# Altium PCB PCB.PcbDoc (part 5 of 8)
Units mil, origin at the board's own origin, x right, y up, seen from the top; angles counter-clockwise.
Board outline 11229.24 x 7764.43 mil, 14 copper layers (Top Layer, GND1, Signal 1, GND2, Signal 2, GND3, Singal 3, Power 1, GND4, Power 2, GND5, Power 3, GND6, Bottom Layer), stack 91.892 mil thick; 877 components, 305 nets, 2660 pads, 2851 vias.
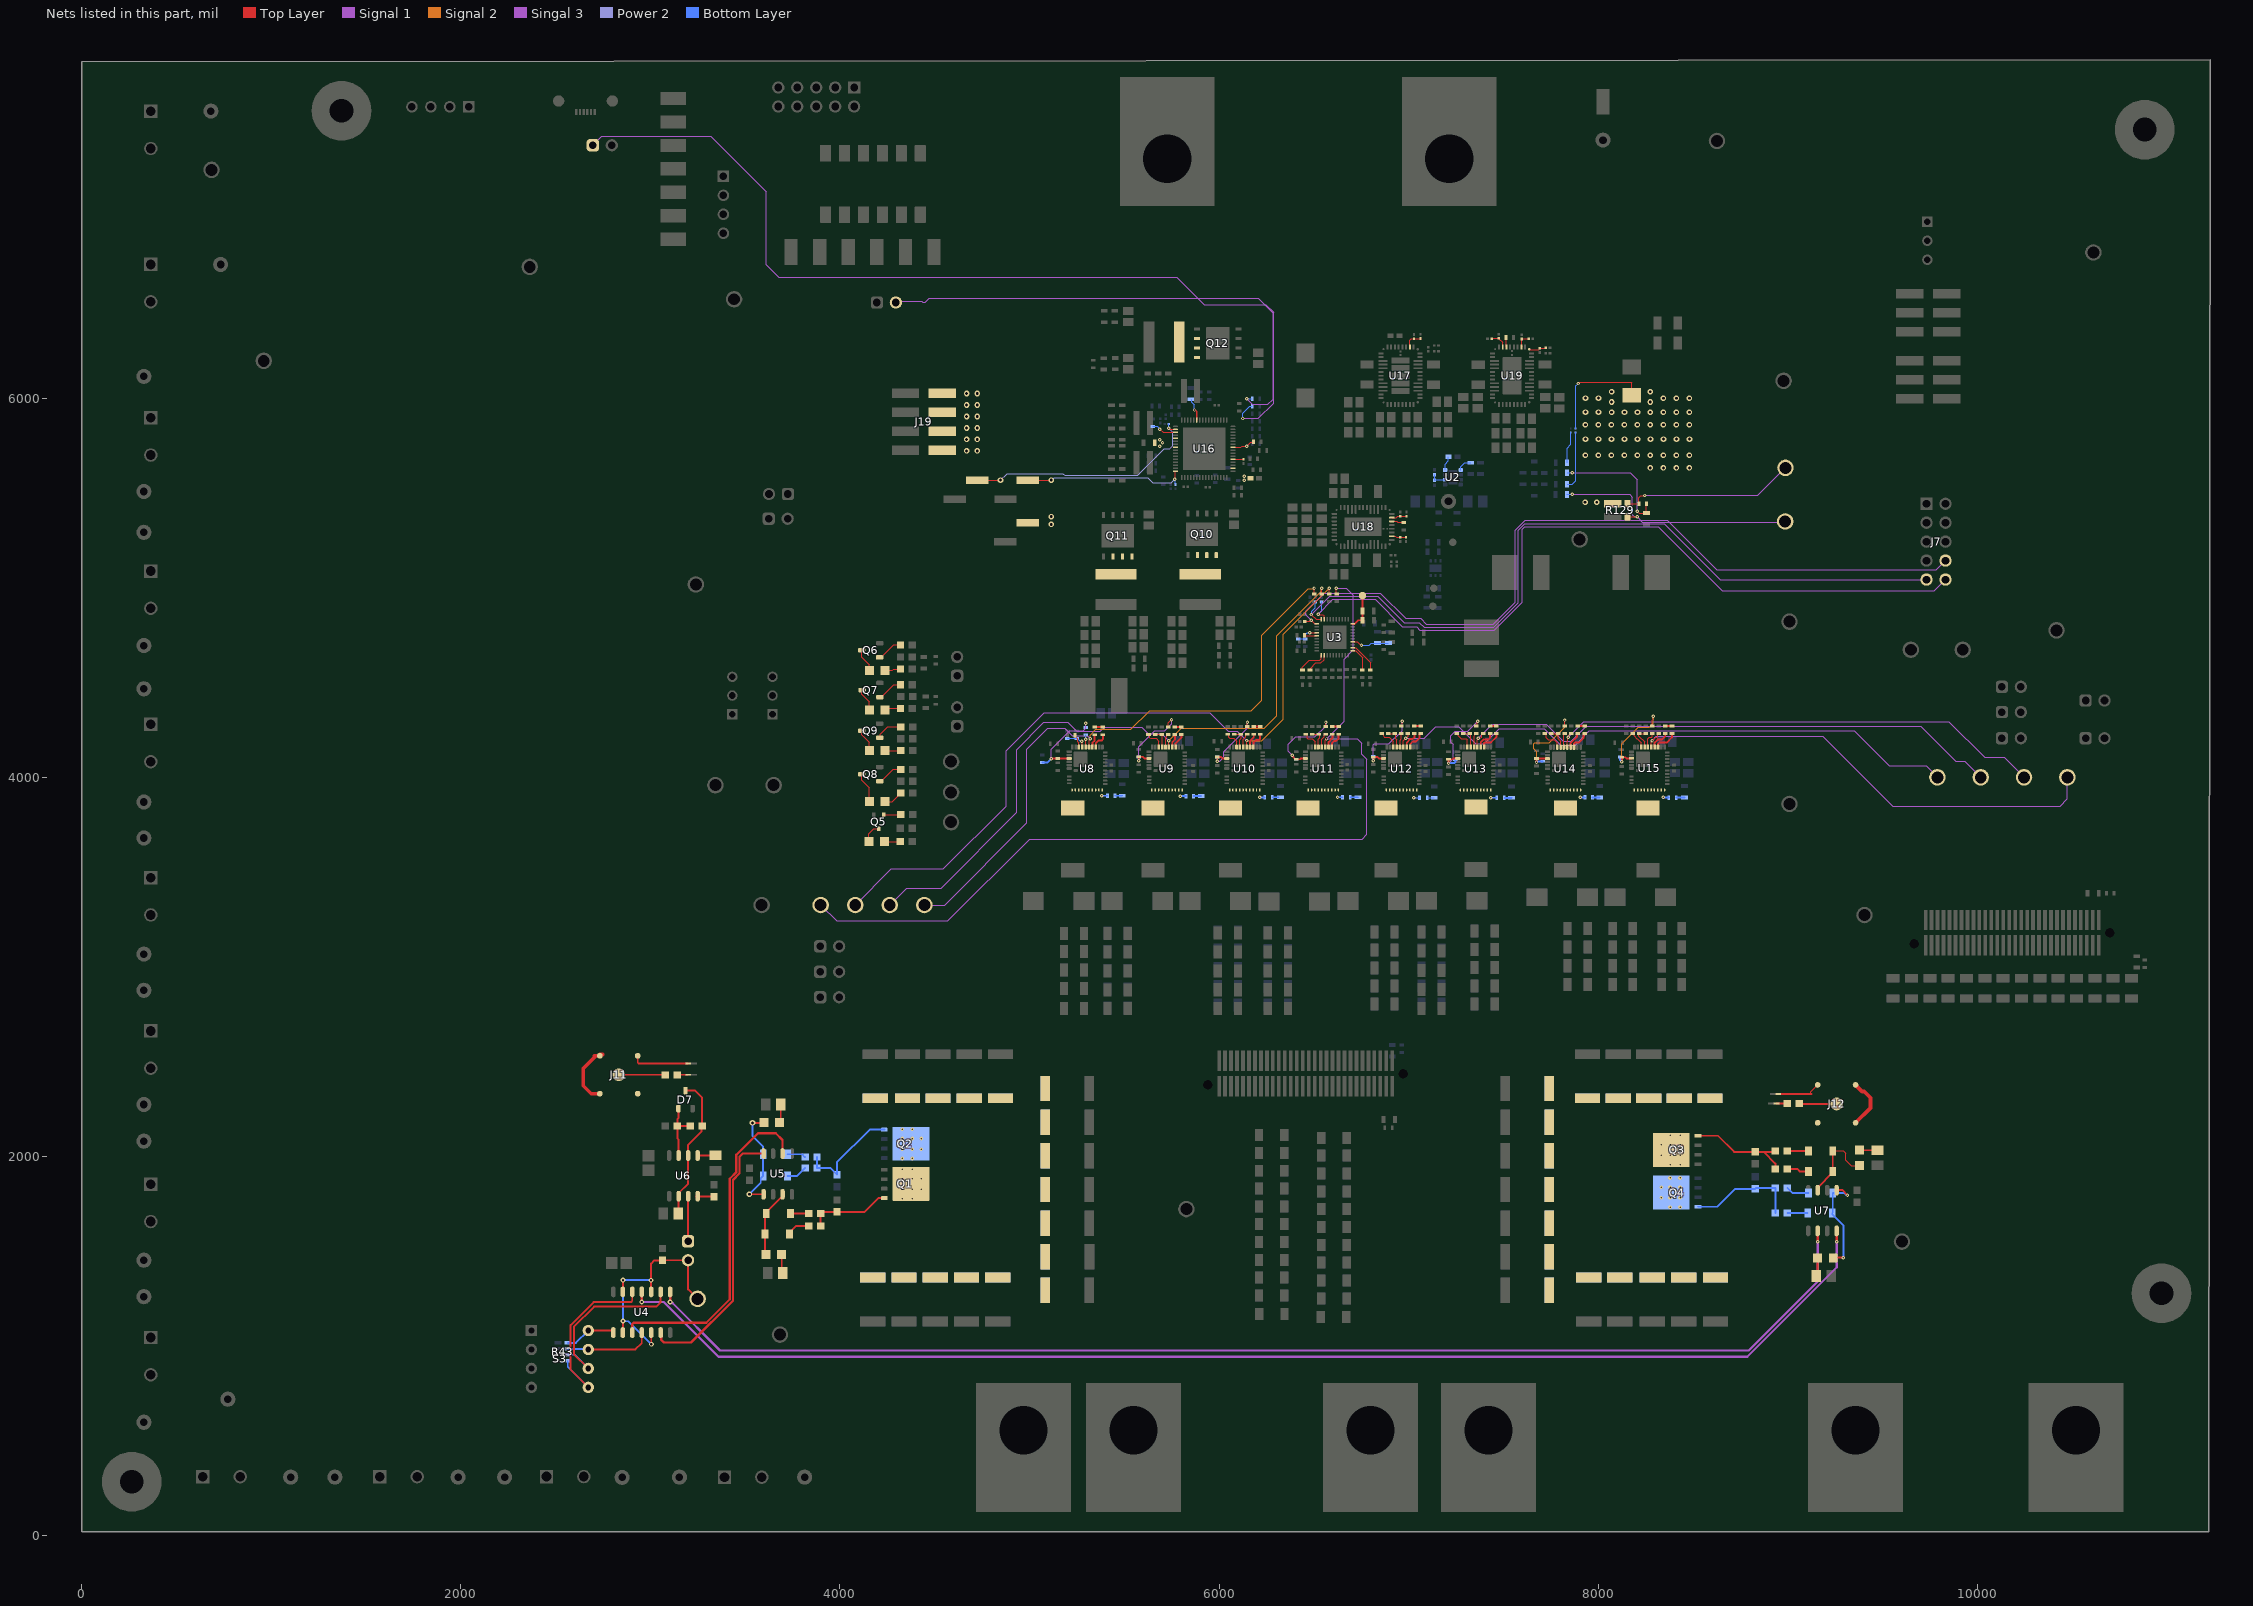
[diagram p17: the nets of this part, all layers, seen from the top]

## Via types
v1: diameter 30, hole 15, Top Layer to Bottom Layer, 1251 vias
v2: diameter 18, hole 8, Top Layer to Bottom Layer, tented both sides, 472 vias
v3: diameter 32, hole 16, Top Layer to Bottom Layer, 464 vias
v4: diameter 30, hole 15, Top Layer to Bottom Layer, tented both sides, 326 vias
v5: diameter 19.68, hole 7.87, Top Layer to Bottom Layer, 323 vias
v6: diameter 26, hole 12, Top Layer to Bottom Layer, tented both sides, 12 vias
v7: diameter 14, hole 6, Top Layer to Bottom Layer, tented both sides, 2 vias
v8: diameter 18, hole 8, Top Layer to Bottom Layer, 1 vias

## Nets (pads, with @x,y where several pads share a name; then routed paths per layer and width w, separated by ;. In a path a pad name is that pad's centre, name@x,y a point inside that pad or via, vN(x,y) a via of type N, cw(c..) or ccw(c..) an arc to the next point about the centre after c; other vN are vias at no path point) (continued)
MODE2-U4: R242.1 R245.1 U19.38 | length 89.1
  Top Layer w6: U19.38@7639.91,6257.54 7641.31,6256.14 7647.41,6256.14 7647.91,6256.64 7685.53,6256.64 7688.2,6259.31 7688.99,6259.31 7692.29,6262.61 R242.1@7692.29,6263.4 7693.17,6264.28 7723.3,6264.28 R245.1@7724.18,6265.16
NetC8_1: C8.1 U2.8 | length 77.5
  Bottom Layer w6: U2.8@7192.15,5620.99 7192.15,5652.53 7210.35,5670.72 C8.1@7210.35,5691
NetC16_1: C16.1 R17.1 TP8.1 U3.40 | length 189.8
  Top Layer w10: U3.40@6704.62,4809.13 6715.64,4809.13 6735.12,4828.6 C16.1@6756.79,4828.6 6756.79,4876.58 R17.1@6756.32,4877.05 6756.32,4957.32 TP8.1@6756.8,4957.8
NetC28_1: C28.1 U6.5 | length 95.5
  Top Layer w10: U6.5@3249.16,2004.66 3344.37,2004.66 C28.1@3344.56,2004.85
NetC29_1: C29.1 D7.3 R117.1 U6.2 U6.6 | length 766.5
  Top Layer w10: C29.1@3146.64,1699.1 3149.16,1701.62 U6.2@3149.16,1790.09 3149.16,1806.83 3199.16,1856.83 U6.6@3199.16,2004.66 3199.16,2061.16 3269,2131 3269,2155.56 R117.1@3273.18,2159.73 3273.18,2310.05 3236.49,2346.74 D7.3@3185.24,2346.74
NetC82_1: C82.1 R26.1 R128.1 | length 654.6
  Top Layer w6: v2(8205.63,5402.4) 8208.88,5402.4 8217.78,5393.5 C82.1@8254.9,5393.5 R128.1@8254.9,5442.9
  Singal 3 w6: v2(7864.1,5606) 7864.39,5605.71 8169.73,5605.71 8205.63,5569.8 v2(8205.63,5402.4)
  Bottom Layer w6: R26.1@7835.91,5605.71 7836.2,5606 v2(7864.1,5606)
NetC171_1: C171.1 L2.1 U8.10 U8.11 U8.12 U8.13 U8.14 U8.15 U8.16 U8.17 U8.18 U8.19 | length 31.5
  Bottom Layer w10: v2@5380.43,3902.65 v2(5380.37,3902.59) C171.1@5411.78,3902.59
NetC171_2: C171.2 R147.2 | length 37.5
  Bottom Layer w6: R147.2@5488.57,3902.59 R147.2@5488.63,3902.65
  Bottom Layer w10: C171.2@5452.02,3902.36 C171.2@5451.78,3902.59 R147.2@5488.57,3902.59 ; R147.2@5488.63,3902.65 R147.2@5488.87,3902.41
NetC184_1: C184.1 R148.2 R152.2 U8.3 | length 474.5
  Top Layer w10: v2(5115.5,4098.1) 5116.63,4099.23 C184.1@5148.25,4099.23 U8.3@5209.67,4099.24
  Signal 1 w6: v2(5115.5,4098.1) 5115.5,4148.27 5212.53,4245.3 5283.1,4245.3 5297.36,4259.56 v2(5297.36,4284.39)
  Bottom Layer w6: R148.2@5297.36,4263.12 v2(5297.36,4284.39)
  Bottom Layer w10: R152.2@5068.1,4078.26 5095.66,4078.26 v2(5115.5,4098.1)
NetC185_2: C185.2 R153.2 U8.36 | length 113.1
  Top Layer w6: v2@5277.44,4188.84 5277.44,4160.42 U8.36@5278.57,4159.28
  Bottom Layer w6: C185.2@5199.29,4204.65 R153.2@5248.68,4204.65 5253.18,4204.65 5265.56,4192.27 5274,4192.27 v2(5276.3,4189.97)
NetC186_1: C186.1 R154.2 | length 43.9
  Top Layer w10: C186.1@5343.53,4264.47 R154.2@5387.38,4264.47
NetC186_2: C186.2 U8.33 | length 70.3
  Top Layer w10: U8.33@5331.72,4159.28 5331.72,4181.76 5343.76,4193.81 5343.76,4224.24 C186.2@5343.53,4224.47
NetC187_1: C187.1 L3.1 U9.10 U9.11 U9.12 U9.13 U9.14 U9.15 U9.16 U9.17 U9.18 U9.19 | length 31.3
  Bottom Layer w6: C187.1@5825.09,3900.84 C187.1@5826.09,3901.84
  Bottom Layer w10: v2(5795.18,3900.84) C187.1@5825.09,3900.84
NetC187_2: C187.2 R155.2 | length 42.7
  Bottom Layer w6: R155.2@5905.68,3900.84 R155.2@5906.69,3901.84
  Bottom Layer w10: C187.2@5865.09,3900.84 R155.2@5905.68,3900.84 ; C187.2@5866.09,3901.84 C187.2@5866.61,3901.33
NetC198_1: C198.1 R156.2 R159.2 U9.3 | length 463.9
  Top Layer w6: R156.2@5731.89,4265.93 5731.89,4286.8 5749.02,4303.93 v2(5749.2,4303.93)
  Top Layer w10: v2(5576.28,4087.06) 5576.28,4108.05 C198.1@5576.35,4108.13 5596.81,4108.13 5599.22,4105.72 5605.7,4099.24 U9.3@5630.91,4099.24
  Signal 1 w6: v2(5576.28,4087.06) 5576.28,4161.03 5660.55,4245.3 5712.92,4245.3 5749.2,4281.58 v2(5749.2,4303.93)
  Bottom Layer w10: v2(5576.28,4087.06) R159.2@5576.28,4107.15
NetC201_2: C201.2 R161.2 U9.36 | length 98
  Top Layer w6: C201.2@5668.57,4225.93 R161.2@5699.41,4225.93 ; R161.2@5699.51,4225.93 R161.2@5700.71,4224.73 ; U9.36@5699.81,4159.28 R161.2@5699.81,4224.73
NetC202_1: C202.1 R162.2 | length 33.2
  Top Layer w10: C202.1@5768.61,4265.93 R162.2@5801.85,4265.93
NetC202_2: C202.2 U9.33 | length 72.3
  Top Layer w10: U9.33@5752.96,4159.28 5752.96,4185.65 5766.57,4199.25 C202.2@5766.57,4225.93
NetC203_1: C203.1 L4.1 U10.10 U10.11 U10.12 U10.13 U10.14 U10.15 U10.16 U10.17 U10.18 U10.19 | length 27.4
  Bottom Layer w6: C203.1@6240.69,3894.19 C203.1@6241,3894.5
  Bottom Layer w10: v2(6213.74,3894.19) C203.1@6240.69,3894.19
NetC203_2: C203.2 R163.2 | length 34
  Bottom Layer w10: C203.2@6281,3894.5 R163.2@6314.96,3894.5
NetC215_1: C215.1 R164.2 R167.2 U10.3 | length 399
  Top Layer w6: R164.2@6149.77,4267.16 6149.93,4267.32 v2(6149.93,4290.19)
  Top Layer w10: v2(5990.27,4084.69) 5990.27,4105.96 C215.1@5990.53,4106.22 6011.29,4106.22 6018.27,4099.24 U10.3@6041.07,4099.24
  Signal 1 w6: v2(5990.27,4084.69) 5990.47,4084.89 6003.53,4084.89 6025.93,4107.29 6025.93,4133.38 6149.93,4257.39 v2(6149.93,4290.19)
  Bottom Layer w6: R167.2@5990.27,4106.03 R167.2@5990.4,4106.16
  Bottom Layer w10: v2(5990.27,4084.69) R167.2@5990.27,4106.03
NetC217_2: C217.2 R169.2 U10.36 | length 100.2
  Top Layer w6: R169.2@6083.28,4227.16 6116.53,4227.16 6116.53,4204.92 6109.96,4198.35 U10.36@6109.96,4162.88
NetC218_1: C218.1 R170.2 | length 33.2
  Top Layer w10: C218.1@6183.02,4267.16 R170.2@6216.26,4267.16
NetC218_2: C218.2 U10.33 | length 72.5
  Top Layer w10: U10.33@6163.11,4162.88 6163.11,4190.07 6183.02,4209.97 C218.2@6183.02,4227.16
NetC219_1: C219.1 L5.1 U11.10 U11.11 U11.12 U11.13 U11.14 U11.15 U11.16 U11.17 U11.18 U11.19 | length 26.9
  Bottom Layer w10: v2(6625.01,3894.49) C219.1@6651.87,3894.5
NetC219_2: C219.2 R171.2 | length 41.3
  Bottom Layer w6: R171.2@6732.77,3894.5 R171.2@6733.08,3894.19
  Bottom Layer w10: C219.2@6691.87,3894.5 R171.2@6732.77,3894.5
NetC232_1: C232.1 R172.2 R176.2 U11.3 | length 456.3
  Top Layer w6: R172.2@6561.72,4267.16 6561.72,4284.85 6564.03,4287.16 v2(6564.03,4290.4)
  Top Layer w10: v2(6385.74,4116.3) 6388.03,4114 6388.03,4110.12 6403.13,4095.03 6427.28,4095.03 6431.5,4099.24 U11.3@6455.46,4099.24
  Signal 1 w6: v2(6385.74,4116.3) 6365.32,4136.71 6365.32,4172.92 6405.01,4212.61 6505.15,4212.61 6564.3,4271.76 6564.3,4290.14 v2(6564.03,4290.4)
  Bottom Layer w6: v2@6388.03,4110.12 6403.13,4095.03 R176.2@6407.63,4095.03
NetC233_2: C233.2 R177.2 U11.36 | length 94.6
  Top Layer w6: R177.2@6497.98,4227.16 6531.23,4227.16 6531.23,4208.26 6524.36,4201.39 U11.36@6524.36,4168.66
NetC234_1: C234.1 R178.2 | length 33.2
  Top Layer w10: C234.1@6597.71,4267.16 R178.2@6630.96,4267.16
NetC234_2: C234.2 U11.33 | length 76.2
  Top Layer w10: U11.33@6577.51,4159.28 6577.51,4185.81 6597.71,4206.02 C234.2@6597.71,4227.16
NetC235_1: C235.1 L6.1 U12.10 U12.11 U12.12 U12.13 U12.14 U12.15 U12.16 U12.17 U12.18 U12.19 | length 30.2
  Bottom Layer w6: v2(7028.07,3891.41) C235.1@7058.32,3891.41
NetC235_2: C235.2 R179.2 | length 38
  Bottom Layer w6: C235.2@7098.32,3891.41 7135.65,3891.41 R179.2@7136.11,3891.87
NetC247_1: C247.1 R180.2 R183.2 U12.3 | length 441.2
  Top Layer w6: R180.2@6965.42,4270.49 v2(6965.42,4295.57)
  Top Layer w10: v2(6813.95,4086.79) 6813.95,4105.68 C247.1@6813.67,4105.96 6836.02,4105.96 6842.42,4099.56 6867.8,4099.56 U12.3@6868.12,4099.24
  Signal 1 w6: v2(6813.95,4086.79) 6813.95,4170.93 6819.94,4176.93 6896.29,4176.93 6965.42,4246.05 v2(6965.42,4295.57)
  Bottom Layer w6: v2(6813.95,4086.79) R183.2@6813.95,4110.15
NetC249_2: C249.2 R185.2 U12.36 | length 98.4
  Top Layer w6: C249.2@6899.03,4230.49 6932.22,4230.49 6932.22,4202.35 6937.02,4197.55 U12.36@6937.02,4167.23
NetC250_1: C250.1 R186.2 | length 33.2
  Top Layer w10: C250.1@7031.8,4270.49 R186.2@7064.99,4270.49
NetC250_2: C250.2 U12.33 | length 88
  Top Layer w10: U12.33@6990.17,4167.23 6990.17,4183.2 7009.32,4202.35 7022.07,4202.35 7031.8,4212.08 C250.2@7031.8,4230.49
NetC251_1: C251.1 L7.1 U13.10 U13.11 U13.12 U13.13 U13.14 U13.15 U13.16 U13.17 U13.18 U13.19 | length 31.1
  Bottom Layer w6: C251.1@7464.31,3891.99 C251.1@7464.9,3891.41
  Bottom Layer w10: v2(7434.01,3891.99) C251.1@7464.31,3891.99
NetC251_2: C251.2 R187.2 | length 39.2
  Bottom Layer w10: C251.2@7504.9,3891.41 R187.2@7543.17,3891.41 R187.2@7542.54,3892.04
NetC263_1: C263.1 R188.2 R191.2 U13.3 | length 478.4
  Top Layer w6: R188.2@7363.18,4270.49 7363.18,4295.2 v2(7363.97,4295.99)
  Top Layer w10: v2(7210.58,4074.91) 7210.58,4094.75 C263.1@7210.42,4094.91 7231.66,4094.91 7235.99,4099.24 U13.3@7258.81,4099.24
  Signal 1 w6: v2(7210.58,4074.91) 7234.4,4098.74 7234.4,4174.2 7223.4,4185.2 7223.4,4220 7246.2,4242.8 7310.77,4242.8 v2(7363.97,4295.99)
  Bottom Layer w10: v2(7210.58,4074.91) 7240.89,4074.91 7246.84,4080.86 R191.2@7246.84,4092.91
NetC265_2: C265.2 R193.2 U13.36 | length 98.4
  Top Layer w6: C265.2@7296.69,4230.49 7323.21,4230.49 7327.71,4225.99 U13.36@7327.71,4160.48
NetC266_1: C266.1 R194.2 | length 33.1
  Top Layer w10: C266.1@7429.67,4270.49 R194.2@7462.73,4270.49
NetC266_2: C266.2 U13.33 | length 105.4
  Top Layer w10: U13.33@7380.86,4160.48 7380.86,4185.11 7394.16,4198.41 7420.09,4198.41 7429.67,4207.99 C266.2@7429.67,4230.49
NetC267_1: C267.1 L8.1 U14.10 U14.11 U14.12 U14.13 U14.14 U14.15 U14.16 U14.17 U14.18 U14.19 | length 25.4
  Bottom Layer w10: v2(7905.58,3893.8) C267.1@7931.01,3893.8
NetC267_2: C267.2 R195.2 | length 36.9
  Bottom Layer w10: C267.2@7971.01,3893.8 R195.2@8007.93,3893.8
NetC279_2: C279.2 R201.2 U14.36 | length 106.3
  Top Layer w6: R201.2@7757.64,4230.1 7785.68,4230.1 C279.2@7784.21,4230.1 ; C279.2@7788.4,4230.1 7788.4,4202.72 7801.8,4189.33 U14.36@7801.8,4158.89
NetC281_1: C281.1 R196.2 R200.2 U14.3 | length 483.5
  Top Layer w6: R196.2@7823.33,4270.1 v2(7823.33,4301.9)
  Top Layer w10: v2(7674.72,4080) C281.1@7674.72,4099.56 7675.08,4099.21 7732.54,4099.21 U14.3@7732.9,4098.85
  Signal 2 w6: v2(7674.72,4080) 7674.72,4135.45 7660.03,4150.14 7660.03,4176.89 7666.24,4183.11 7742.14,4183.11 7823.33,4264.3 v2(7823.33,4301.9)
  Bottom Layer w10: v2(7674.72,4080) 7677.97,4080 7682.14,4084.17 R200.2@7706.6,4084.17
NetC282_1: C282.1 R202.2 | length 32.8
  Top Layer w10: C282.1@7889.03,4270.1 R202.2@7921.87,4270.1
NetC282_2: C282.2 U14.33 | length 85.3
  Top Layer w10: U14.33@7854.95,4158.89 7854.95,4180.94 7889.03,4215.02 C282.2@7889.03,4230.1
NetC283_1: C283.1 L9.1 U15.10 U15.11 U15.12 U15.13 U15.14 U15.15 U15.16 U15.17 U15.18 U15.19 | length 29.5
  Bottom Layer w6: C283.1@8371.33,3893.8 C283.1@8372.02,3893.12
  Bottom Layer w10: v2(8342.8,3893.8) C283.1@8371.33,3893.8
NetC283_2: C283.2 R203.2 | length 43.6
  Bottom Layer w6: C283.2@8412.02,3893.12 C283.2@8412.2,3893.3
  Bottom Layer w10: C283.2@8412.2,3893.3 R203.2@8455.5,3893.3
NetC294_1: C294.1 R204.2 R207.2 U15.3 | length 502
  Top Layer w6: R204.2@8285.77,4270.1 8285.77,4300.3 8291.46,4305.98 v2(8291.46,4321.3)
  Top Layer w10: v2(8125.2,4081.7) C294.1@8125.2,4105.38 8143.7,4105.38 8149.51,4099.56 U15.3@8175.92,4099.56
  Signal 2 w6: v2(8125.2,4081.7) 8125.2,4177.85 8156.52,4209.17 8156.52,4209.32 8211.5,4264.3 8270.4,4264.3 8291.46,4285.36 v2(8291.46,4321.3)
  Bottom Layer w10: R207.2@8115.4,4106.3 8115.4,4091.5 v2(8125.2,4081.7)
NetC297_2: C297.2 R209.2 U15.36 | length 116
  Top Layer w6: C297.2@8216.62,4230.1 8215.39,4228.87 8215.39,4217.11 8244.82,4187.68 U15.36@8244.82,4159.6 ; C297.2@8225.63,4230.1 R209.2@8258.41,4230.1
NetC298_1: C298.1 R210.2 | length 32.8
  Top Layer w10: C298.1@8356.73,4270.1 R210.2@8389.51,4270.1
NetC298_2: C298.2 U15.33 | length 108.6
  Top Layer w10: U15.33@8297.53,4158.89 8297.53,4182.87 8313.55,4198.9 8335.48,4198.9 8353.69,4217.11 8353.69,4227.06 C298.2@8356.73,4230.1
NetC352_1: C352.1 U16.53 | length 55.3
  Top Layer w6: U16.53@6073.37,5677.33 C352.1@6128.7,5677.3
NetC382_1: C382.1 U18.44 | length 66.1
  Top Layer w6: U18.44@6911.43,5350.26 6936.52,5350.26 6942.64,5344.15 C382.1@6974.96,5344.15
NetC389_1: C389.1 U19.44 | length 51.3
  Top Layer w6: C389.1@7513.82,6320.04 7516.11,6317.75 U19.44@7516.11,6269.66
NetD1_1: D1.1 R74.1 | length 121.9
  Top Layer w10: D1.1@3733.83,1590.83 3733.83,1596.84 3769.99,1633 R74.1@3834.72,1633
NetD1_2: D1.2 D3.1 D4.1 U5.7 | length 360.2
  Top Layer w10: D3.1@3610.16,1482.56 3604.89,1487.83 3604.89,1692.97 D4.1@3611.03,1699.1 3611.03,1705.1 3686.62,1780.7 3690.75,1780.7 3697.04,1786.99 U5.7@3697.04,1800.04
NetD2_1: D2.1 R75.1 | length 98.2
  Bottom Layer w10: D2.1@3723.99,2010.99 3800.04,2010.99 3815.03,1996 R75.1@3816.02,1996
NetD2_2: D2.2 D5.1 D6.1 U5.5 | length 565.6
  Top Layer w10: v4(3522.1,1800.04) U5.5@3597.04,1800.04 ; v4(3539.1,2176.7) 3597.77,2176.7 D6.1@3599.14,2178.07
  Bottom Layer w10: v4(3522.1,1800.04) 3582.04,1859.98 3582.04,1884.37 D5.1@3595.05,1897.38 D2.2@3595.05,2010.99 3595.05,2050.01 3589,2056.06 3589,2056.84 3539.1,2106.74 v4(3539.1,2176.7)
NetD3_2: D3.2 R76.1 | length 101.2
  Top Layer w10: D3.2@3692.84,1482.56 3692.84,1390.82 R76.1@3699.52,1384.14
NetD4_2: D4.2 R77.1 | length 94.8
  Top Layer w10: D4.2@3739.96,1699.1 R77.1@3834.72,1699.1
NetD5_2: D5.2 R78.1 | length 108.8
  Bottom Layer w10: D5.2@3723.99,1897.38 3774.59,1897.38 3815.03,1937.82 R78.1@3816.02,1937.82
NetD6_2: D6.2 R81.1 | length 97.1
  Top Layer w10: D6.2@3681.81,2178.07 3687.72,2183.97 R81.1@3687.72,2272.73
NetD7_1: D7.1 R84.1 R117.2 U6.7 | length 320.8
  Top Layer w10: D7.1@3147.84,2252.25 3147.84,2202.06 3142.48,2196.7 3142.48,2160.02 R84.1@3142.2,2159.73 ; U6.7@3149.16,2004.66 3149.16,2088.6 3142.2,2095.56 R84.1@3142.2,2159.73 ; R117.2@3210.18,2159.73 R84.1@3142.2,2159.73
NetD8_1: D8.1 R118.1 | length 110.7
  Top Layer w10: R118.1@8998.17,2029.32 D8.1@9108.9,2029.32
NetD8_2: D8.2 D10.1 D11.1 U7.7 | length 435.8
  Top Layer w6: D8.2@9237.83,2029.32 9291.84,2029.32 9305.05,2016.11 9305.05,1980.66 9334.88,1950.84 D10.1@9379.71,1950.84
  Top Layer w10: U7.7@9158.21,1821.64 9158.21,1835.42 9237.83,1915.05 D11.1@9237.83,1921.05 D8.2@9237.83,2029.32
NetD9_1: D9.1 R119.1 | length 121
  Bottom Layer w10: R119.1@8998.17,1832.39 8999.15,1832.39 9023.83,1807.71 D9.1@9108.9,1807.71
NetD9_2: D9.2 D12.1 D13.1 U7.5 | length 571.1
  Top Layer w10: D13.1@9240.19,1464.28 9242.01,1466.1 v2(9293.4,1466.1) ; U7.5@9258.21,1821.64 9289.65,1821.64 v2(9315.29,1796)
  Bottom Layer w10: v2(9293.4,1466.1) 9293.4,1636.66 9234.78,1695.28 D12.1@9234.78,1701.28 9237.83,1704.34 D9.2@9237.83,1807.71 9298.16,1807.71 9309.88,1796 v2(9315.29,1796)
NetD10_2: D10.2 R120.1 | length 74.4
  Top Layer w10: D10.2@9398.33,2032.24 R120.1@9472.77,2032.24
NetD11_2: D11.2 R121.1 | length 116.1
  Top Layer w10: R121.1@8998.17,1934.05 9049.42,1934.05 9062.41,1921.05 D11.2@9108.9,1921.05
NetD12_2: D12.2 R122.1 | length 107.7
  Bottom Layer w10: R122.1@8998.17,1701.28 D12.2@9105.84,1701.28
NetD13_2: D13.2 R127.2 | length 97.2
  Top Layer w10: R127.2@9150.82,1369.87 9157.51,1376.56 D13.2@9157.51,1464.28
NetD14_1: D14.1 R130.1 | length 83.9
  Top Layer w6: D14.1@4238.34,4563.54 4275.76,4563.54 4282.58,4570.36 R130.1@4319.42,4570.36
NetD14_2: D14.2 Q6.3 | length 122.6
  Top Layer w6: Q6.3@4115.39,4669.5 Q6.3@4115.39,4669.5 4115.43,4634.19 4155.66,4593.96 D14.2@4155.66,4563.54
NetD15_1: D15.1 R131.1 | length 84.9
  Top Layer w6: D15.1@4238.34,4353.9 4247.54,4363.1 R131.1@4319.41,4363.1
NetD15_2: D15.2 Q7.3 | length 126.1
  Top Layer w6: Q7.3@4115.39,4463.3 4115.39,4439.21 4155.66,4398.94 D15.2@4155.66,4353.9
NetD16_1: D16.1 R132.1 | length 82.1
  Top Layer w6: D16.1@4238.34,4140.5 4320.2,4140.5 R132.1@4320.35,4140.35
NetD16_2: D16.2 Q9.3 | length 122.1
  Top Layer w6: Q9.3@4115.39,4245.95 4115.39,4224.47 4155.66,4184.2 D16.2@4155.66,4140.5
NetD17_1: D17.1 R134.1 | length 116.2
  Top Layer w6: D17.1@4222.69,3872 4275.63,3872 R134.1@4320.39,3916.76
NetD17_2: D17.2 Q8.3 | length 161.2
  Top Layer w6: Q8.3@4115.43,4016.53 4115.43,3985.54 4155.66,3945.31 D17.2@4155.66,3872
NetD18_1: D18.1 Q5.3 | length 103.6
  Top Layer w6: D18.1@4152.83,3661.08 4152.83,3702.43 4178.6,3728.2 Q5.3@4204.38,3728.2
NetD18_2: D18.2 R144.2 | length 83.7
  Top Layer w6: D18.2@4235.51,3661.08 R144.2@4319.18,3661.08
NetJ8_1: J8.1 U6.3 | length 238
  Top Layer w10: J8.1@3198.77,1552.25 3199.16,1552.64 U6.3@3199.16,1790.09
NetJ8_2: J8.2 R116.2 TP13.1 U4.2 U4.5 U4.10 U4.13 | length 1327.4
  Top Layer w10: U4.2@2854.4,1070.52 2854.97,1071.09 2854.97,1131.46 v6(2855.54,1132.03) ; U4.13@2854.4,1285.08 2854.97,1285.65 2854.97,1346.46 v6(2855.54,1347.03) ; U4.5@3004.4,1070.52 3004.75,1070.17 3004.75,1009.15 v6(3005.1,1008.8) ; U4.10@3004.4,1285.08 3004.1,1285.38 3004.1,1346.3 v6(3003.8,1346.6) 3003.8,1434.8 3020.07,1451.07 R116.2@3063.33,1451.07 3064.52,1452.25 J8.2@3198.77,1452.25 3198.77,1298.69 TP13.1@3249.16,1248.3
  Bottom Layer w10: v6(3003.8,1346.6) 3003.59,1346.81 2855.75,1346.81 v6(2855.54,1347.03) v6(2855.54,1132.03) 2857.21,1130.36 2883.54,1130.36 v6(3005.1,1008.8)
NetJ11_1: J11.1 R145.2 | length 247.1
  Top Layer w10: J11.1@2833.24,2430.69 3077,2430.69 R145.2@3079.37,2428.32
NetJ11_2: J11.2 J11.3 J11.4 J11.5 NT5.2 | length 639.4
  Top Layer w10: J11.4@2933.24,2530.69 2933.24,2495.24 2939.1,2489.38 NT5.2@3200.02,2489.38
  Top Layer w20: 2704.46,2530.69 J11.3@2733.24,2530.69 ; 2713.84,2530.69 2646.2,2463.05 2646.2,2372.76 2688.24,2330.72 J11.2@2733.24,2330.69 ; J11.3@2733.24,2537.26 2748.8,2537.26
NetJ12_1: J12.1 R146.2 | length 210.5
  Top Layer w10: R146.2@9048.79,2280.19 9051.97,2277.01 J12.1@9258,2277.01
NetJ12_2: J12.2 J12.3 J12.4 J12.5 NT6.2 | length 510.1
  Top Layer w6: 9121.36,2327.87 9121.36,2340.37 J12.5@9158,2377.01
  Top Layer w10: NT6.2@8950.8,2329.7 9125.48,2329.7
  Top Layer w20: J12.3@9358,2177.01 9436.2,2255.21 9436.2,2309.6 9403.45,2342.35 9392.66,2342.35 J12.2@9358,2377.01
NetJ29_1: J29.1 R221.2 | length 4987.1
  Singal 3 w6: J29.1@2696.5,7334 2742.9,7380.4 3317.7,7380.4 3610.5,7087.6 3610.5,6703.9 3677.2,6637.2 5778,6637.2 5851.2,6564 5921.7,6493.5 6247.4,6493.5 6288,6452.9 6288,5974 6206.7,5892.7 v2(6125.34,5892.7)
  Bottom Layer w6: v2(6125.34,5892.7) 6125.34,5920.16 6161.81,5956.64 6174.47,5956.64 R221.2@6174.8,5956.98
NetL1_2: L1.2 NT2.1 R129.1 | length 597.2
  Top Layer w6: v2(7893.89,6077.13) 7895.53,6077.13 7903.41,6085 8173.58,6085 8177.1,6081.49 L1.2@8177.1,6015.33
  Bottom Layer w6: NT2.1@7881.1,5839.36 7881.1,6064.34 v2(7893.89,6077.13)
  other v1: 7931.1,5451.2 7992.2,5451.2 8275.2,5632.1 8343.83,5632.1 8412.47,5632.1 7932.47,5699.1 8001.1,5699.1 8069.73,5699.1 8138.37,5699.1 8207,5699.1 8275.2,5699.1 8343.83,5699.1 8412.47,5699.1 7933.3,5783.9 8001.93,5783.9 8070.57,5783.9 8139.2,5783.9 8207.83,5783.9 8276.03,5783.9 8344.67,5783.9 8413.3,5783.9 7932.47,5859.51 8001.1,5859.51 8069.73,5859.51 8138.37,5859.51 8207,5859.51 8275.2,5859.51 8343.83,5859.51 8412.47,5859.51 7933.3,5926.28 8001.93,5926.28 8070.96,5925.53 8139.04,5925.53 8207.12,5925.53 8275.2,5925.53 8343.83,5925.9 8412.47,5925.9 7933.3,5999.98 8001.93,5999.98 8343.83,5999.6 8412.47,5999.6
  other v4: 8481.1,5632.1 8481.1,5699.1 8481.93,5783.9 8481.1,5859.51 8481.1,5925.9 8070.96,5979.52 8275.2,5979.52 8481.1,5999.6 8070.96,6033.51 8275.2,6033.51
NetL10_1: L10.1 Q10.6 Q10.7 Q10.8
NetL11_1: L11.1 Q11.6 Q11.7 Q11.8
NetL12_1: L12.1 Q12.6 Q12.7 Q12.8
NetNT1_2: NT1.2 R24.1 | length 168.9
  Bottom Layer w6: R24.1@7835.91,5658.39 7836.2,5658.68 7836.2,5737.05 7855.14,5755.99 NT1.2@7855.14,5819.36
NetNT2_2: NT2.2 R29.1 | length 308
  Bottom Layer w6: R29.1@7835.91,5545.7 7862.63,5545.7 7881.1,5564.17 NT2.2@7881.1,5819.36
NetNT3_2: NT3.2 R145.1 | length 58.2
  Top Layer w10: R145.1@3142,2430.2 3142.48,2430.69 NT3.2@3200.02,2430.69
NetNT4_2: NT4.2 R146.1 | length 57.5
  Top Layer w6: R146.1@8996.37,2278.57 R146.1@8997.6,2279.8
  Top Layer w10: NT4.2@8940.61,2278.57 R146.1@8996.37,2278.57
NetQ1_4: Q1.4 R74.2 R77.2 R79.2 | length 436
  Top Layer w10: R74.2@3897.71,1633 R77.2@3897.71,1699.1 3905.58,1706.97 R79.2@3984.32,1706.97 4129.88,1706.97 4202.66,1779.75 Q1.4@4234.2,1779.75
NetQ1_5: Q1.5 Q1.6 Q1.7 Q1.8 Q1.9@4375.17,1854.75 R39.1 R40.1 R44.1 R45.1 R46.1 R47.1 R48.1 R49.1 R50.1 R51.1 R52.1 R53.1 R54.1 R55.1 R56.1 R57.1 R58.1
  other v5: 4328.88,1777.59 4381.64,1777.59 4328.88,1826.6 4381.64,1826.6 4428.49,1826.6 4328.88,1882.9 4381.64,1882.9 4428.49,1882.9 4328.88,1931.92 4381.64,1931.92
NetQ2_4: Q2.4 R75.2 R78.2 R80.2 | length 563.7
  Bottom Layer w10: R75.2@3879.01,1996 R78.2@3879.01,1937.82 3950.87,1937.82 R80.2@3984.33,1904.37 ; R80.2@3984.33,1903.38 R80.2@3984.33,1904.37 ; Q2.4@4234.2,2141.03 4157.05,2141.03 3984.33,1968.3 R80.2@3984.33,1904.37
NetQ2_5: Q2.5 Q2.6 Q2.7 Q2.8 Q2.9@4375.17,2066.03 R41.1 R42.1 R59.1 R60.1 R61.1 R62.1 R63.1 R64.1 R65.1 R66.1 R67.1 R68.1 R69.1 R70.1 R71.1 R72.1 R73.1
  other v5: 4328.88,1988.86 4381.64,1988.86 4328.88,2037.88 4381.64,2037.88 4428.49,2037.88 4328.88,2094.18 4381.64,2094.18 4428.49,2094.18 4328.88,2143.19 4381.64,2143.19
NetQ3_4: Q3.4 R118.2 R121.2 R124.2 | length 561.3
  Top Layer w10: Q3.4@8526.69,2108.71 8632.17,2108.71 8717.57,2023.32 R124.2@8828.88,2023.32 8873.28,2023.32 ; R121.2@8935.18,1934.05 8934.71,1934.52 8934.71,1961.89 8873.28,2023.32 ; R118.2@8935.18,2029.32 8929.18,2023.32 8873.28,2023.32
NetQ3_5: Q3.5 Q3.6 Q3.7 Q3.8 Q3.9@8385.71,2033.71 R86.1 R87.1 R88.1 R89.1 R90.1 R91.1 R92.1 R93.1 R94.1 R95.1 R96.1 R97.1 R98.1 R99.1 R100.1 R125.1 R126.1
  other v5: 8379.25,1956.55 8432,1956.55 8332.4,2005.56 8379.25,2005.56 8432,2005.56 8332.4,2061.86 8379.25,2061.86 8432,2061.86 8379.25,2110.88 8432,2110.88
NetQ4_4: Q4.4 R119.2 R122.2 R123.2 | length 580.2
  Bottom Layer w10: Q4.4@8526.69,1734.31 8627.76,1734.31 8721.98,1828.53 R123.2@8828.88,1828.53 8832.74,1832.39 R119.2@8935.18,1832.39 R122.2@8935.18,1701.28
NetQ4_5: Q4.5 Q4.6 Q4.7 Q4.8 Q4.9@8385.71,1809.31 R82.1 R83.1 R101.1 R102.1 R103.1 R104.1 R105.1 R106.1 R107.1 R108.1 R109.1 R110.1 R111.1 R112.1 R113.1 R114.1 R115.1
  other v5: 8379.25,1732.14 8432,1732.14 8332.4,1781.16 8379.25,1781.16 8432,1781.16 8332.4,1837.45 8379.25,1837.45 8432,1837.45 8379.25,1886.47 8432,1886.47
NetQ5_1: Q5.1 R139.1 | length 90.5
  Top Layer w6: Q5.1@4229.97,3803 4320.2,3803 R139.1@4320.39,3802.81
NetQ6_1: Q6.1 R141.1 | length 138
  Top Layer w6: Q6.1@4209.88,4632.1 4217.75,4632.1 4285.05,4699.4 4317.91,4699.4 R141.1@4319.41,4697.9
NetQ7_1: Q7.1 R142.1 | length 135.4
  Top Layer w6: Q7.1@4211.04,4422.6 4218.92,4422.6 4284.28,4487.96 R142.1@4319.41,4487.96
NetQ8_1: Q8.1 R140.1 | length 136.3
  Top Layer w6: Q8.1@4209.92,3979.13 4217.79,3979.13 4280.03,4041.37 R140.1@4320.39,4041.37
NetQ9_1: Q9.1 R143.1 | length 143.1
  Top Layer w6: Q9.1@4209.88,4208.55 4211.9,4210.57 4211.9,4225.84 4251.71,4265.65 R143.1@4320.35,4265.65
NetR3_1: R3.1 R6.2 U2.6 | length 89.2
  Bottom Layer w6: R3.1@7136.95,5566.61 7140.16,5569.81 U2.6@7192.15,5569.81 7193.42,5569.81 U2.6@7193.59,5569.64 ; R6.2@7136.95,5595.54 7136.95,5566.87 7137.09,5566.74 R3.1@7138.69,5565.14
NetR4_1: R4.1 U2.1 | length 79.8
  Bottom Layer w6: U2.1@7274.83,5620.99 7274.83,5638.22 7295.84,5659.22 R4.1@7328.7,5659.22
NetR7_2: R7.2 U3.21 | length 150.4
  Top Layer w6: R7.2@6440.11,4566.38 6440.11,4579.83 6476.57,4616.29 6531.08,4616.29 6539.27,4624.48 U3.21@6539.27,4643.78
NetR9_2: R9.2 U3.22 | length 124.6
  Top Layer w6: R9.2@6479.67,4566.38 6482.79,4569.5 6482.79,4576.35 6510.02,4603.58 6537.34,4603.58 6554.94,4621.17 6554.94,4643.69 U3.22@6555.02,4643.78
NetR11_2: R11.2 U3.32 | length 166.6
  Top Layer w6: U3.32@6704.62,4683.15 6721.51,4683.15 6801.08,4603.58 R11.2@6801.08,4566.38
NetR12_2: R12.2 U3.31 | length 131.7
  Top Layer w6: U3.31@6704.62,4667.4 6719.92,4667.38 6757.17,4630.13 R12.2@6757.17,4566.38
NetR13_2: R13.2 R14.2 U3.34 | length 200.6
  Top Layer w6: U3.34@6705.04,4714.64 6730.19,4714.64 6748.01,4696.81 v2(6751.26,4696.81)
  Bottom Layer w6: v2(6751.26,4696.81) 6793.12,4696.81 6804.2,4707.9 R14.2@6836.07,4707.9 6893.56,4707.9 R13.2@6893.65,4707.98
NetR18_2: R18.2 R19.2 U3.14 | length 121.2
  Top Layer w6: v2(6479,4763.14) 6479.63,4762.51 6515.02,4762.51 U3.14@6515.65,4761.89
  Bottom Layer w6: R18.2@6421.33,4729.59 R19.2@6454.62,4729.59 6454.62,4750.86 6466.22,4762.46 6478.33,4762.46 v2(6479,4763.14)
NetR21_2: R21.2 U3.15 | length 65.4
  Top Layer w6: R21.2@6451.3,4748.7 6453.86,4746.14 U3.15@6515.65,4746.14
NetR38_1: R38.1 R129.4 TP15.1 | length 1318.5
  Top Layer w6: R129.4@8154.06,5374.14 v2(8205.63,5374.14)
  Signal 1 w6: v2(8205.63,5374.14) 8233.37,5346.4 8983.7,5346.4 TP15.1@8986.7,5349.4
  Singal 3 w6: v2(7864.1,5492.41) 8165.79,5492.41 8180.7,5477.5 8180.7,5385.8 8192.27,5374.23 8205.54,5374.23 v2(8205.63,5374.14)
  Bottom Layer w6: R38.1@7835.4,5491.9 7835.91,5492.41 v2(7864.1,5492.41)
NetR43_1: R43.1 S3.8 U4.1 | length 274.3
  Top Layer w10: S3.8@2672.4,1081.3 2798.11,1081.3 2804.4,1075.01 U4.1@2804.4,1070.52
  Bottom Layer w10: R43.1@2564.09,1016.34 2607.44,1016.34 S3.8@2672.4,1081.3
NetR43_2: R43.2 S3.7 U4.4 | length 461.5
  Top Layer w10: S3.7@2672.4,981.3 2921.04,981.3 2954.4,1014.66 U4.4@2954.4,1070.52
  Bottom Layer w10: R43.2@2564.09,984.85 2565.86,983.07 2670.63,983.07 S3.7@2672.4,981.3
NetR43_3: R43.3 S3.6 U4.9 | length 954.9
  Top Layer w10: S3.6@2672.4,881.3 2596.6,957.1 2596.6,1101.6 2703,1208 3030.7,1208 3054.4,1231.7 U4.9@3054.4,1285.08
  Bottom Layer w10: R43.3@2564.09,953.35 2600.35,953.35 S3.6@2672.4,881.3
NetR43_4: R43.4 S3.5 U4.12 | length 978.8
  Top Layer w10: S3.5@2672.4,781.3 2578.6,875.1 2578.6,1109.5 2700.8,1231.7 2898.54,1231.7 2904.4,1237.56 U4.12@2904.4,1285.08
  Bottom Layer w10: R43.4@2564.09,921.86 2564.09,889.61 S3.5@2672.4,781.3
NetR85_1: R85.1 U6.4 | length 87.3
  Top Layer w10: U6.4@3250.83,1787.33 R85.1@3334.72,1787.33
  Top Layer w20: U6.4@3249.16,1790.09 3249.16,1789 U6.4@3250.83,1787.33
NetR128_2: R128.2 R129.3 TP14.1 | length 931.3
  Top Layer w6: R129.3@8154.06,5443.03 8214.77,5443.03 R128.2@8214.9,5442.9 8214.9,5474.9 8225.1,5485.1 8244.5,5485.1 v2(8246.1,5486.7)
  Signal 1 w6: v2(8246.1,5486.7) 8842.8,5486.7 TP14.1@8988.2,5632.1
NetR148_1: R148.1 U8.35 | length 64.3
  Top Layer w6: U8.35@5296.29,4159.28 5296.29,4198.66 v2(5297.2,4199.57)
  Bottom Layer w6: v2(5297.2,4199.57) 5297.2,4222.97 R148.1@5297.36,4223.12
NetR149_2: R149.2 U8.37 | length 71.9
  Top Layer w6: R149.2@5239.62,4222.4 5239.62,4217.9 5253.67,4203.85 5253.67,4188.56 5260.85,4181.38 U8.37@5260.85,4159.28
NetR150_1: R150.1 TP31.1 U8.34 | length 3307.3
  Top Layer w6: U8.34@5314,4159.28 5314,4194.36 5319.87,4200.22 v2(5319.87,4203.47) ; R150.1@6501.01,4968.57 v2(6501.01,4997.1)
  Signal 2 w6: v2(5319.87,4203.47) 5319.87,4222.45 5350.32,4252.9 5535.22,4252.9 5633.48,4351.15 6168.71,4351.15 6224.15,4406.6 6224.15,4747.93 6471.03,4994.8 6498.71,4994.8 v2(6501.01,4997.1)
  Singal 3 w6: TP31.1@4445,3325.8 4552.84,3325.8 4986,3758.96 4986,4147.59 5096.41,4258 5187,4258 5225.9,4219.1 5262.65,4219.1 5262.69,4219.05 5304.29,4219.05 v2(5319.87,4203.47)
NetR154_1: R154.1 U8.32 | length 88.8
  Top Layer w10: U8.32@5349.44,4159.28 5349.49,4159.34 5349.49,4178.32 5365.75,4194.58 5381.52,4194.58 5387.38,4200.44 R154.1@5387.38,4223.12
NetR156_1: R156.1 U9.35 | length 78.3
  Top Layer w6: U9.35@5717.53,4159.28 5717.53,4208.2 5723.46,4214.13 5723.46,4221.43 5727.96,4225.93 R156.1@5735.26,4225.93
NetR157_2: R157.2 U9.37 | length 103.4
  Top Layer w6: R157.2@5634.53,4225.93 5634.53,4209.43 5639.22,4204.74 5668.34,4204.74 5682.1,4190.98 U9.37@5682.1,4159.28
NetR158_1: R158.1 TP33.1 U9.34 | length 3582.6
  Top Layer w6: U9.34@5735.25,4159.28 v2(5735.25,4193.43) ; R158.1@6541.83,4967.31 v2(6541.83,4997.1)
  Signal 2 w6: v2(5735.25,4193.43) 5800.79,4258.97 6237.95,4258.97 6304.73,4325.75 6304.73,4747 6540.19,4982.46 6540.19,4995.46 v2(6541.83,4997.1)
  Singal 3 w6: TP33.1@4262.87,3325.8 4352.77,3415.7 4533.4,3415.7 4931.9,3814.2 4931.9,4146.32 5075.77,4290.19 5200.95,4290.19 5249.1,4242.05 5373.65,4242.05 5395.8,4264.2 5591.6,4264.2 5625.68,4230.12 5698.56,4230.12 v2(5735.25,4193.43)
NetR162_1: R162.1 U9.32 | length 79.3
  Top Layer w10: U9.32@5770.68,4159.28 5770.68,4179.1 5800.87,4209.29 5800.87,4225.55 R162.1@5801.25,4225.93
NetR164_1: R164.1 U10.35 | length 75.3
  Top Layer w6: U10.35@6127.68,4162.88 6127.68,4200.08 6142.15,4214.55 6142.15,4222.66 6146.65,4227.16 R164.1@6149.77,4227.16
NetR165_2: R165.2 U10.37 | length 95
  Top Layer w6: R165.2@6050.04,4227.16 6050.04,4210.63 6055.51,4205.16 6078.04,4205.16 6092.25,4190.95 U10.37@6092.25,4162.88
NetR166_1: R166.1 TP35.1 U10.34 | length 3808.2
  Top Layer w6: U10.34@6145.4,4162.88 v2(6145.4,4193.76) ; R166.1@6581.51,4967.2 v2(6581.51,4997.1)
  Signal 2 w6: v2(6145.4,4193.76) 6224.23,4193.76 6337.7,4307.23 6337.7,4753.29 v2(6581.51,4997.1)
  Singal 3 w6: TP35.1@4080.74,3325.8 4271.14,3516.2 4546,3516.2 4876.6,3846.8 4876.6,4138.99 5078.55,4340.93 5951.9,4340.93 6048.78,4244.05 6095.1,4244.05 v2(6145.4,4193.76)
NetR170_1: R170.1 U10.32 | length 86.6
  Top Layer w10: U10.32@6180.83,4162.88 6180.83,4181.57 6195.44,4196.18 6208.48,4196.18 6216.26,4203.96 R170.1@6216.26,4227.16
NetR172_1: R172.1 U11.35 | length 70.4
  Top Layer w6: U11.35@6542.08,4168.66 6542.08,4201.29 6555.47,4214.68 6555.47,4222.66 6559.97,4227.16 R172.1@6564.47,4227.16
NetR173_2: R173.2 U11.37 | length 89.4
  Top Layer w6: R173.2@6464.74,4227.16 6464.74,4206.55 6468.25,4203.04 6491.29,4203.04 6506.61,4187.72 6506.61,4168.69 U11.37@6506.64,4168.66
NetR174_1: R174.1 TP37.1 U11.34 | length 4775.7
  Top Layer w6: U11.34@6559.79,4168.66 6559.79,4194.97 v2(6566.87,4202.04) ; R174.1@6619.1,4969.18 v2(6619.1,4997.1)
  Signal 1 w6: v2(6566.87,4202.04) 6660.53,4295.7 6660.53,4623.82 6708.8,4672.09 6708.8,4959.55 6671.25,4997.1 v2(6619.1,4997.1)
  Singal 3 w6: TP37.1@3898.6,3325.8 3982.4,3242 4568,3242 5000.2,3674.2 6754.5,3674.2 6778.49,3698.19 6778.49,4095.31 6751.64,4122.15 6751.64,4179.15 6728.75,4202.04 v2(6566.87,4202.04)
NetR178_1: R178.1 U11.32 | length 90
  Top Layer w10: U11.32@6595.23,4159.28 6595.23,4180.56 6605.99,4191.32 6618.41,4191.32 6630.96,4203.87 R178.1@6630.96,4227.16
NetR180_1: R180.1 U12.35 | length 66.3
  Top Layer w6: U12.35@6954.74,4167.23 6954.74,4196.09 6961.99,4203.33 R180.1@6961.99,4230.49
NetR181_2: R181.2 U12.37 | length 100.4
  Top Layer w6: R181.2@6865.84,4230.49 6867.78,4228.56 6867.78,4215.66 6872.11,4211.32 6897.67,4211.32 6919.31,4189.69 U12.37@6919.31,4167.23
NetR182_1: R182.1 TP39.1 U12.34 | length 3142.2
  Top Layer w6: U12.34@6972.46,4167.23 6972.46,4192.16 v2(6985.13,4204.83) 6997.81,4217.51 6997.81,4229.69 R182.1@6998.61,4230.49
  Singal 3 w6: v2(6985.13,4204.83) 7081.34,4204.83 7142.87,4266.36 7264.42,4266.36 7353.51,4177.27 7398.88,4177.27 7477.77,4256.16 7716.23,4256.16 7802.31,4170.09 7878.96,4170.09 7954.08,4245.2 9350.98,4245.2 9536.49,4059.7 9729.86,4059.7 TP39.1@9789.75,3999.8
NetR186_1: R186.1 U12.32 | length 99.1
  Top Layer w10: U12.32@7007.89,4167.23 7008.72,4168.05 7008.72,4174.9 7023.16,4189.35 7039.54,4189.35 7057.99,4207.8 7057.99,4227.99 7060.49,4230.49 R186.1@7064.99,4230.49
NetR188_1: R188.1 U13.35 | length 78.5
  Top Layer w6: U13.35@7345.43,4160.48 7345.43,4217.24 7349.02,4220.83 7349.02,4225.99 7353.52,4230.49 R188.1@7358.68,4230.49
NetR189_2: R189.2 U13.37 | length 111.7
  Top Layer w6: R189.2@7253.3,4230.1 7257.04,4230.1 7261.54,4225.6 7261.54,4218.11 7276.42,4203.23 7304.36,4203.23 7309.99,4197.6 U13.37@7309.99,4160.48
NetR190_1: R190.1 TP41.1 U13.34 | length 2957.8
  Top Layer w6: U13.34@7363.14,4159.28 7363.14,4197.21 7368.71,4202.78 7368.71,4206.02 7370,4207.31 7381.16,4207.31 7384.67,4210.83 7384.67,4225.99 7389.17,4230.49 R190.1@7396.42,4230.49
  Singal 3 w6: v2(7368.1,4205.41) 7368.58,4205.41 7442.08,4278.91 7726.52,4278.91 7815.61,4189.82 7858.19,4189.82 7937.64,4269.27 9701.73,4269.27 9885.9,4085.1 9932.94,4085.1 TP41.1@10018.24,3999.8
NetR194_1: R194.1 U13.32 | length 115.5
  Top Layer w10: U13.32@7398.58,4160.48 7398.58,4179.9 7402.09,4183.41 7434.46,4183.41 7462.73,4211.68 R194.1@7462.73,4230.49
NetR196_1: R196.1 U14.35 | length 71
  Top Layer w6: U14.35@7819.51,4158.89 R196.1@7819.51,4229.88
NetR197_2: R197.2 U14.37 | length 114.1
  Top Layer w6: R197.2@7724.79,4230.1 7725.3,4229.59 7725.3,4209.62 7736.02,4198.9 7767.35,4198.9 7784.08,4182.17 U14.37@7784.08,4158.89
NetR198_1: R198.1 TP43.1 U14.34 | length 2639.2
  Top Layer w6: U14.34@7837.23,4158.89 7837.65,4159.31 7837.65,4189.85 7840.7,4192.9 7840.7,4208.55 7845.29,4213.14 7845.29,4221.59 7853.8,4230.1 R198.1@7856.18,4230.1
  Singal 3 w6: v2(7843,4210.85) 7924.57,4292.42 9850.8,4292.42 10038.32,4104.9 10141.62,4104.9 TP43.1@10246.72,3999.8
NetR202_1: R202.1 U14.32 | length 103.5
  Top Layer w10: U14.32@7872.66,4158.89 7873,4159.23 7873,4177.65 7879.02,4183.67 7899.34,4183.67 7921.87,4206.2 R202.1@7921.87,4230.1
NetR204_1: R204.1 U15.35 | length 87.8
  Top Layer w6: U15.35@8262.53,4159.6 8262.53,4203.61 8269.22,4210.3 8282.26,4210.3 8285.77,4213.82 R204.1@8285.77,4230.1
NetR205_2: R205.2 U15.37 | length 92.3
  Top Layer w6: R205.2@8180.55,4227.54 8188.19,4227.54 8190.13,4225.6 8190.13,4217.96 8204.86,4203.24 8204.93,4203.24 8226.5,4181.67 8226.5,4159.05 U15.37@8226.66,4158.89
NetR206_1: R206.1 TP45.1 U15.34 | length 2579
  Top Layer w6: U15.34@8280.25,4159.6 8280.25,4186.2 8284.1,4190.06 v2(8284.1,4193.3) ; v2@8284.49,4193 8284.49,4193.69 8302.7,4211.9 8311.44,4211.9 8314.96,4215.42 8314.96,4225.6 8319.46,4230.1 R206.1@8323.96,4230.1
  Singal 3 w6: v2(8284.1,4193.3) 8306.16,4215.36 9185.24,4215.36 9552.9,3847.7 10437.5,3847.7 10475.2,3885.4 TP45.1@10475.2,3999.8
NetR210_1: R210.1 U15.32 | length 124.3
  Top Layer w10: U15.32@8315.24,4158.89 8316.51,4160.15 8316.51,4175.22 8325.19,4183.9 8363.29,4183.9 8389.51,4210.12 R210.1@8389.51,4230.1
NetR214_1: R214.1 U16.19 | length 132.2
  Top Layer w6: v2(5687.61,5836.73) 5705.27,5819.06 U16.19@5770.22,5819.06
  Bottom Layer w6: R214.1@5651.14,5850.65 5673.69,5850.65 v2(5687.61,5836.73)
NetR228_1: R228.1 R229.1 U17.40 | length 99.2
  Top Layer w6: U17.40@7006.41,6269.66 7006.41,6305.57 7015.1,6314.27 7064.87,6314.27 R228.1@7065.77,6313.37
NetR233_1: R233.1 R234.1 U18.40 | length 77.3
  Top Layer w6: U18.40@6911.43,5271.52 6930.41,5271.52 6936.52,5265.41 R234.1@6986.22,5265.41
NetR236_1: R236.1 R239.2 U18.45 | length 80.2
  Top Layer w6: U18.45@6911.43,5369.95 6935.63,5369.95 6942.64,5376.95 R239.2@6988.74,5376.95
NetR240_1: R240.1 R241.1 U19.40 | length 78.2
  Top Layer w6: U19.40@7596.71,6272.34 7595.78,6273.27 7595.78,6311.39 R241.1@7596.71,6312.32 7597.67,6313.28 7632.42,6313.28 R240.1@7633.38,6314.24
NetR243_1: R243.1 R246.2 U19.45 | length 89.7
  Top Layer w6: R243.1@7437.93,6314.14 7438.52,6314.73 7473.22,6314.73 R246.2@7475.11,6312.84 ; R246.2@7475.81,6315.32 7475.81,6314.53 7496.41,6293.93 U19.45@7496.41,6272.34
NetU4_3: U4.3 U5.2 | length 1766.8
  Top Layer w12: U4.3@2904.4,1070.52 2904.4,1114.67 2911.43,1121.7 3294.3,1121.7 3418.52,1245.92 3418.52,1882.26 3453.7,1917.44 3453.7,2008 3568.03,2122.33 3661.37,2122.33 3697.04,2086.65 U5.2@3697.04,2014.6
NetU4_6: U4.6 U5.4 | length 1422.3
  Top Layer w12: U4.6@3054.4,1070.52 3056.62,1068.29 3056.62,1033.21 3072.13,1017.7 3214.34,1017.7 3435.52,1238.88 3435.52,1875.22 3470.7,1910.4 3470.7,1998.3 3487,2014.6 U5.4@3597.04,2014.6
NetU4_8: U4.8 U7.2 | length 6631.4
  Top Layer w12: v6(3104.4,1231.7) U4.8@3104.4,1285.08 ; v2(9158.21,1550.51) U7.2@9158.21,1607.07
  Signal 1 w12: v6(3104.4,1231.7) 3108.19,1231.7 3114.36,1225.53 3118.07,1225.53 3367.8,975.8 8794.56,975.8 9158.21,1339.45 v2(9158.21,1550.51)
NetU4_11: U4.11 U7.4 | length 6864
  Top Layer w12: v6(2954.4,1231.7) U4.11@2954.4,1285.08 ; v2(9258.21,1550.51) U7.4@9258.21,1607.07
  Signal 1 w12: v6(2954.4,1231.7) 3070.46,1231.7 3359.06,943.1 8785.9,943.1 9258.21,1415.41 v2(9258.21,1550.51)
PMB_ALERT#: J7.8 R31.1 U3.11 | length 4194.2
  Top Layer w6: R31.1@6451.59,4822.31 6477.59,4822.31 6483.88,4828.6 v2(6487.1,4828.6) 6505.63,4810.07 6514.71,4810.07 U3.11@6515.65,4809.13
  Singal 3 w6: v2(6487.1,4828.6) 6457.4,4858.3 6457.4,4874.67 6554.53,4971.8 6850.5,4971.8 6984.4,4837.9 7063.03,4837.9 7093.73,4807.2 7446.63,4807.2 7562.8,4923.37 7562.8,5303.06 7615.34,5355.6 8363.96,5355.6 8624.96,5094.6 9783.8,5094.6 J7.8@9832.3,5143.1
PMB_CLK: J7.9 R30.1 U3.10 | length 4066.9
  Top Layer w6: v2(6486.55,4858.5) 6512.45,4832.6 U3.10@6539,4832.6
  Singal 3 w6: v2(6486.55,4858.5) 6584.14,4956.1 6836.81,4956.1 6976.56,4816.35 7056.46,4816.35 7082.39,4790.43 7448.33,4790.43 7578.2,4920.3 7578.2,5302.9 7614,5338.7 8347.6,5338.7 8643.2,5043.1 J7.9@9732.3,5043.1
  Bottom Layer w6: v2(6486.55,4858.5) 6488.39,4860.35 6488.39,4876.5 6506.89,4895 6506.89,4923.38 R30.1@6508.29,4924.78
PMB_DIO: J7.10 R32.1 U3.9 | length 4148.5
  Top Layer w6: v2(6522.7,4860.8) 6525,4858.5 6547.51,4858.5 6555.2,4850.81 U3.9@6555.2,4835.5
  Singal 3 w6: v2(6522.7,4860.8) 6600.4,4938.5 6823.5,4938.5 6967.68,4794.32 7042.42,4794.32 7059.94,4776.8 7452.43,4776.8 7599,4923.37 7599,5307.8 7612.8,5321.6 8316.8,5321.6 8655.1,4983.3 9772.5,4983.3 J7.10@9832.3,5043.1
  Bottom Layer w6: v2@6521.5,4862.2 6524.1,4862.2 6540.67,4878.77 R32.1@6540.67,4924.78
POWER_EN: J24.2 R215.1 | length 2680.7
  Signal 1 w6: J24.2@4295.1,6504.5 4302.33,6511.73 4432.13,6511.73 4437.26,6506.6 4451.34,6506.6 4470.94,6526.2 6206.9,6526.2 6285,6448.1 6285,5995 6257.76,5967.76 6174.14,5967.76 v2(6145.44,5996.47)
  Bottom Layer w6: v2(6145.44,5996.47) R215.1@6174.8,5996.47
PVIN345_V5ANA: C340.1 C341.1 C349.1 J19.2 J19.4 J19.6 J19.8 U16.11 U16.21 U16.24 U16.57 | length 243.1
  Top Layer w6: U16.57@6073.37,5740.32 6115.01,5740.32 6121.15,5746.46 v2(6146.73,5746.46) 6168.41,5768.15 6180.27,5768.15 C349.1@6181.4,5769.28
  Top Layer w8: v2@5868.7,5942.7 5882.42,5928.98 U16.11@5882.42,5884.02
  Bottom Layer w6: C340.1@5850.22,5993.76 5854.79,5989.2 5854.79,5978.28 5868.7,5964.37 v2@5868.7,5942.7
  other v2: 5687.49,5746.8 5701.8,5764.4 5687.49,5781.45 5870.55,5937.52
  other v4: 4668.3,5721.84 4724.36,5721.84 4668.3,5782.44 4724.36,5782.44 4668.3,5843.03 4724.36,5843.03 4668.3,5903.62 4724.36,5903.62 4668.3,5964.21 4724.36,5964.21 4668.3,6024.8 4724.36,6024.8
PVINLDOA2_A3: C342.1 J21.2 U16.50
  other v2: 6132.53,5567.8 6132.53,5588.8
  other v4: 5114.8,5334.1 5114.8,5374.9
PVINSWA1: C343.1 J22.2 U16.32 | length 868.6
  Top Layer w6: J22.2@4992.15,5566.7 4993.05,5567.6 v4(5114.8,5567.6) ; v2(5765.61,5571.38) 5765.61,5574.63 5770.22,5579.23 U16.32@5770.22,5614.34
  Power 2 w6: v4(5114.8,5567.6) 5118.51,5567.6 5130.31,5579.4 5624.3,5579.4 5649,5554.7 5748.93,5554.7 v2@5765.22,5570.99
  Bottom Layer w6: v2(5765.61,5571.38) 5765.61,5570.31 5770.22,5565.7 C343.1@5770.22,5544.9
PVINSWB1_B2: C344.1 J20.2 U16.18 | length 1272.9
  Top Layer w6: J20.2@4725.01,5567.4 v4(4846.76,5567.4) ; v2(5735.3,5840.78) 5735.85,5840.78 5741.81,5834.81 U16.18@5770.22,5834.81
  Power 2 w6: v4(4846.76,5567.4) 4881.35,5602 5176.3,5602 5185.2,5593.1 5571.18,5593.1 5711.24,5733.16 5738.75,5733.16 5755.14,5749.54 5755.14,5820.94 v2(5735.3,5840.78)
  Bottom Layer w6: v2(5735.3,5840.78) C344.1@5735.3,5863.93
